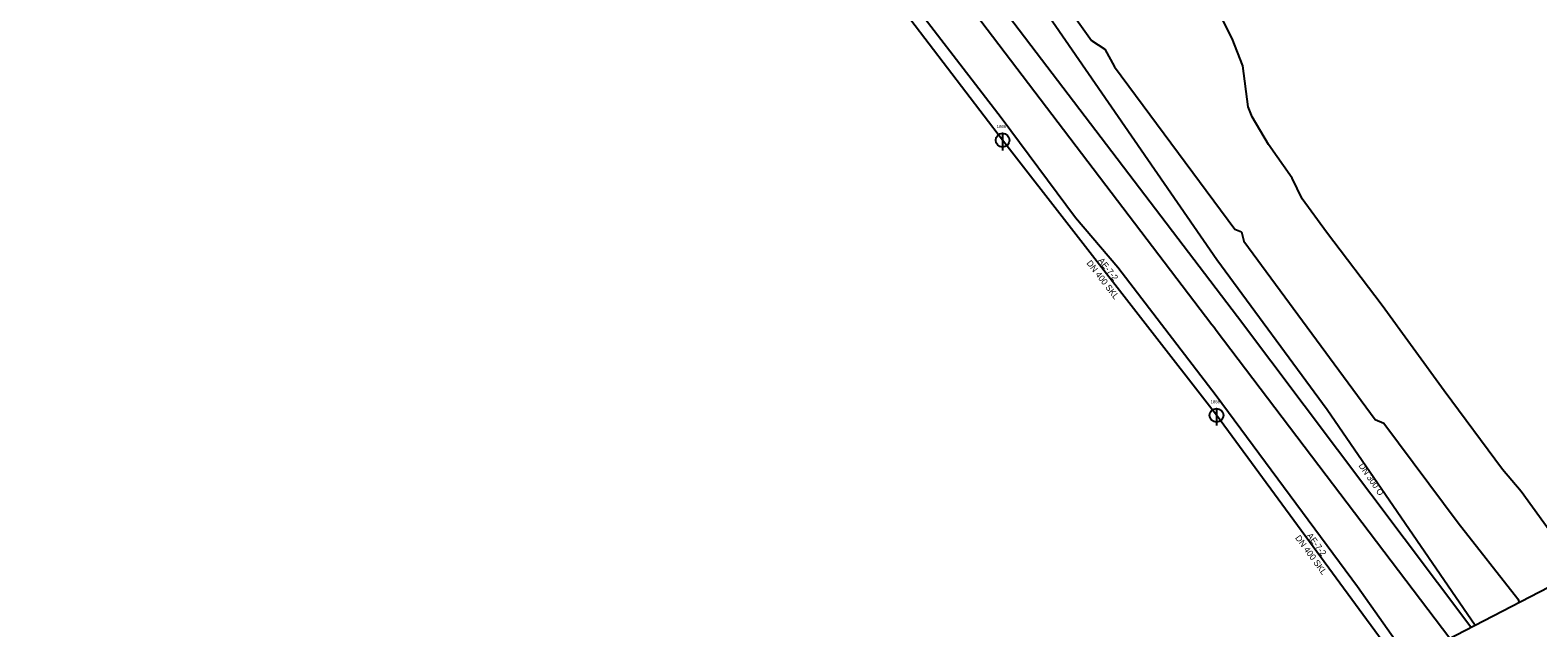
# Model space of a CAD drawing. Extents: x -493753 to -49291, y -1127285 to -112662.
# Drawn here: x -493531.4 to -493312, y -1127171.4 to -1127084.4 of the extents above; entities that cross this region are included whole.
import ezdxf

# ---------------------------------------------------------------- set-up
doc = ezdxf.new("R2010")
doc.units = 0
for name, color, linetype in [('Vrstva 1', 7, 'Continuous'), ('Vrstva 12', 7, 'Continuous'), ('Vrstva 15', 7, 'Continuous'), ('Vrstva 17', 7, 'Continuous'), ('Vrstva 19', 7, 'Continuous'), ('Vrstva 20', 7, 'Continuous'), ('Vrstva 24', 7, 'Continuous'), ('Vrstva 26', 7, 'Continuous'), ('Vrstva 6', 7, 'Continuous')]:
    doc.layers.add(name, color=color, linetype=linetype)

# ---------------------------------------------------------------- blocks, each defined once
blk = doc.blocks.new('_SACH0')
at = {"layer": 'Vrstva 1'}
blk.add_line((0, 0.05), (0, -0.075), dxfattribs=at)
blk.add_circle((0, 0), 0.05, dxfattribs=at)

msp = doc.modelspace()

# ---------------------------------------------------------------- linework, layer by layer
at = {"layer": 'Vrstva 1'}
for points in [[(-493753.13, -1126773.63), (-493540.88, -1127284.87), (-492737.61, -1126868.64), (-492950.39, -1126535.73)], [(-493321.71, -1127171.3), (-493355.7, -1127126.12), (-493396.16, -1127072.91), (-493440.36, -1127015.46), (-493443.8, -1127011.63), (-493444.46, -1127010.85), (-493446.49, -1127008.27), (-493452.76, -1127000), (-493477.07, -1126967.92), (-493488.61, -1126953.19), (-493508.76, -1126886.04), (-493510.25, -1126878.84), (-493511.22, -1126875.6), (-493511.24, -1126875.56), (-493513.66, -1126867.49), (-493514.58, -1126864.18), (-493529.68, -1126809.77)], [(-493449.32, -1127009.16), (-493448.7, -1127009.96), (-493417.13, -1127051.31), (-493359.41, -1127127.23), (-493359.11, -1127127.63), (-493358.81, -1127128.03), (-493324.79, -1127172.89)]]:
    msp.add_lwpolyline(points, dxfattribs=at)
at = {"layer": 'Vrstva 12'}
msp.add_lwpolyline([(-493405.87, -1127076.58), (-493390.1, -1127097.09), (-493379.29, -1127111.66), (-493373.09, -1127118.86), (-493358.81, -1127137.57), (-493338.23, -1127165.37), (-493330.73, -1127175.97)], dxfattribs=at)
at = {"layer": 'Vrstva 15'}
for p, q in [((-493389.89, -1127100.39), (-493422.05, -1127058.22)), ((-493358.75, -1127140.45), (-493389.89, -1127100.39)), ((-493332.11, -1127176.69), (-493358.75, -1127140.45))]:
    msp.add_line(p, q, dxfattribs=at)
at = {"layer": 'Vrstva 20'}
msp.add_lwpolyline([(-493395.54, -1127040.98), (-493406.55, -1127048.37), (-493358.69, -1127117.78), (-493342.63, -1127139.58), (-493321.11, -1127170.99)], dxfattribs=at)
at = {"layer": 'Vrstva 26'}
for p, q in [((-493384.18, -1127075.72), (-493376.93, -1127085.87)), ((-493376.93, -1127085.87), (-493375, -1127087.13)), ((-493375, -1127087.13), (-493374.98, -1127087.14)), ((-493374.98, -1127087.14), (-493373.61, -1127089.72)), ((-493373.61, -1127089.72), (-493356.09, -1127113.34)), ((-493356.09, -1127113.34), (-493355.12, -1127113.74)), ((-493355.12, -1127113.74), (-493355.09, -1127113.75)), ((-493355.09, -1127113.75), (-493354.79, -1127115.09)), ((-493354.79, -1127115.09), (-493335.63, -1127141.04)), ((-493335.63, -1127141.04), (-493334.39, -1127141.57)), ((-493334.39, -1127141.57), (-493323.56, -1127156.08)), ((-493323.56, -1127156.08), (-493314.86, -1127167.19)), ((-493314.86, -1127167.19), (-493314.68, -1127167.66))]:
    msp.add_line(p, q, dxfattribs=at)
at = {"layer": 'Vrstva 6'}
msp.add_lwpolyline([(-493309.43, -1127158.37), (-493314.42, -1127151.56), (-493317.13, -1127148.33), (-493325.6, -1127136.9), (-493334.65, -1127124.45), (-493342.72, -1127113.77), (-493346.29, -1127108.95), (-493347.72, -1127105.92), (-493351.2, -1127101.02), (-493353.58, -1127096.99), (-493354.16, -1127095.54), (-493354.93, -1127089.55), (-493356.45, -1127085.56), (-493360.77, -1127077.02)], dxfattribs=at)

# ---------------------------------------------------------------- block references
at = {"layer": 'Vrstva 17', "xscale": 19.997500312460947, "yscale": 19.997500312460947}
for p in [(-493389.89, -1127100.39), (-493358.75, -1127140.45)]:
    msp.add_blockref('_SACH0', p, dxfattribs=at)

# ---------------------------------------------------------------- texts
at = {"layer": 'Vrstva 19'}
for s, p in [('1865', (-493390.75, -1127098.63)), ('1866', (-493359.62, -1127138.69))]:
    msp.add_text(s, height=0.455, dxfattribs=at).set_placement(p)
for s, rotation, p in [('DN 400 SKL', 307.857, (-493377.73, -1127118.31)), ('AE-7-2', 307.857, (-493376.03, -1127117.94)), ('DN 400 SKL', 306.3184, (-493347.34, -1127158.31)), ('AE-7-2', 306.3184, (-493345.65, -1127157.98))]:
    msp.add_text(s, height=0.91, rotation=rotation, dxfattribs=at).set_placement(p)
at = {"layer": 'Vrstva 24'}
msp.add_text('DN 300 O', height=0.91, rotation=304.417, dxfattribs=at).set_placement((-493338.11, -1127147.78))

doc.saveas('drawing.dxf')
